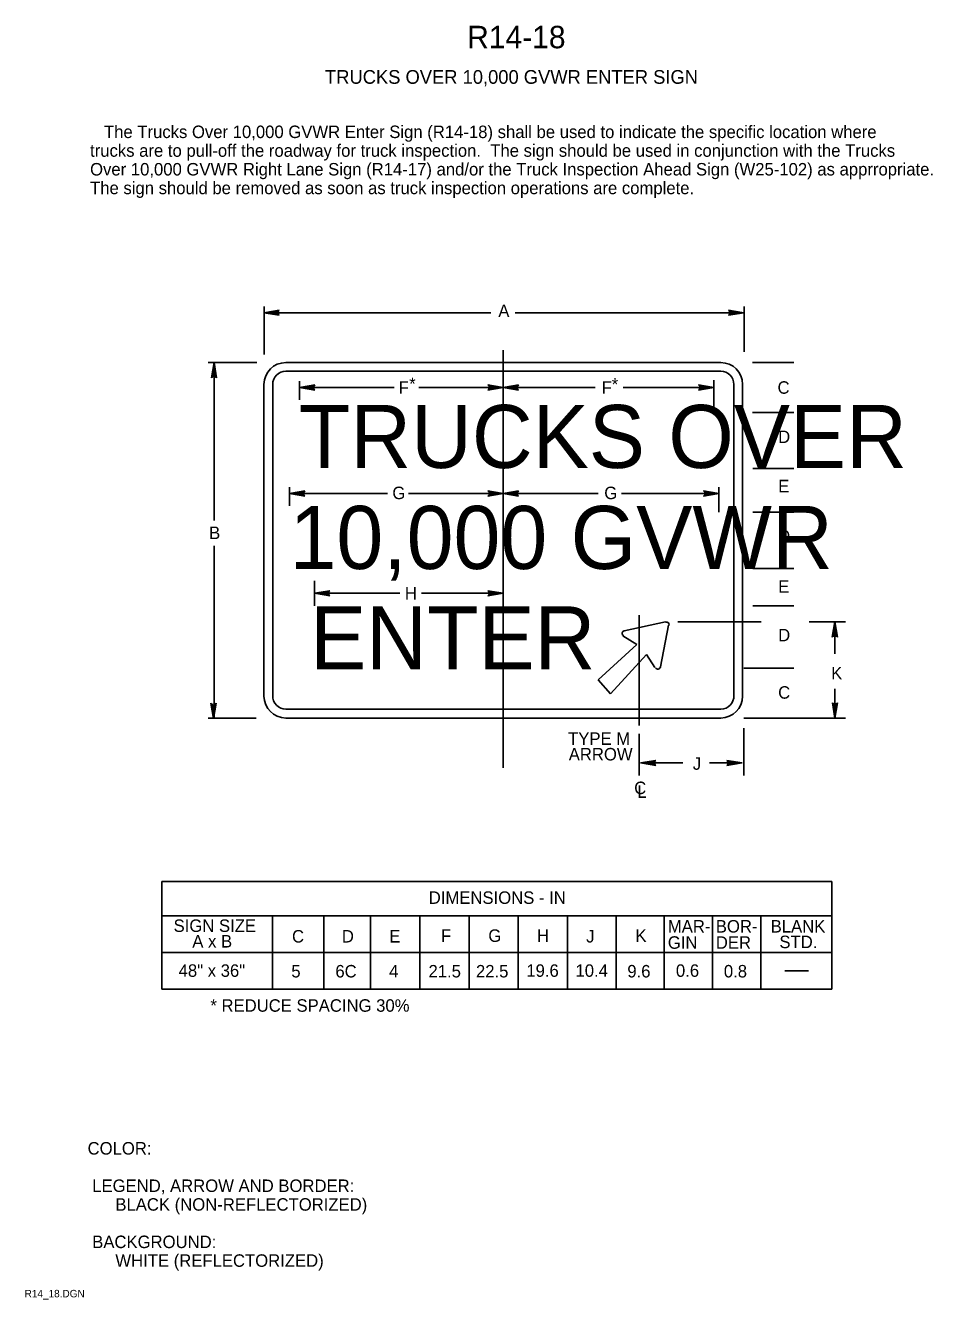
# Model space of a CAD drawing. Extents: x 0.013 to 0.195, y 0.004 to 0.259.
import ezdxf

# ---------------------------------------------------------------- set-up
doc = ezdxf.new("R2010")
doc.units = 0
for name, color, linetype in [('1', 7, 'Continuous'), ('11', 7, 'Continuous'), ('12', 7, 'Continuous'), ('3', 7, 'Continuous')]:
    doc.layers.add(name, color=color, linetype=linetype)

# ---------------------------------------------------------------- blocks, each defined once
blk = doc.blocks.new('RARROW')
at = {"layer": '3'}
for p, q in [((-2.156, 0.28500000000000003), (-2.2665, 0.384625)), ((-2.2665, 0.384625), (0, 0)), ((0, 0), (-2.2665, -0.379125)), ((-2.156, 0.28500000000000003), (-2.075625, 0.12075)), ((0, 0), (-2.156, 0.28500000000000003)), ((-2.14975, -0.2705), (0, 0)), ((-2.075625, 0.12075), (0, 0)), ((0, 0), (-2.074, -0.108)), ((-2.2665, -0.379125), (-2.14975, -0.2705)), ((-2.074, -0.108), (-2.14975, -0.2705))]:
    blk.add_line(p, q, dxfattribs=at)

msp = doc.modelspace()

# ---------------------------------------------------------------- linework, layer by layer
at = {"layer": '11'}
for p, q in [((0.064875, 0.19175), (0.152125, 0.19175)), ((0.0605, 0.187375), (0.0605, 0.124875)), ((0.1565, 0.187375), (0.1565, 0.124875)), ((0.064875, 0.1205), (0.152125, 0.1205))]:
    msp.add_line(p, q, dxfattribs=at)
for centre, radius, start, end in [((0.06487500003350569, 0.18737499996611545), 0.004375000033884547, 90, 180), ((0.1521250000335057, 0.18737500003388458), 0.0043749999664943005, 0, 90), ((0.0648749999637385, 0.12487499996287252), 0.004374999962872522, 180, 270), ((0.1521249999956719, 0.12487500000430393), 0.004375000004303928, 270, 0)]:
    msp.add_arc(centre, radius, start, end, dxfattribs=at)
at = {"layer": '12'}
for p, q in [((0.13275, 0.138), (0.14100000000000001, 0.13975)), ((0.141625, 0.139125), (0.14, 0.13075)), ((0.13525, 0.13525), (0.1325, 0.137)), ((0.1275, 0.128125), (0.13525, 0.13525)), ((0.13725, 0.13325), (0.13, 0.12537500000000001)), ((0.138875, 0.130625), (0.13725, 0.13325)), ((0.13, 0.12537500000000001), (0.1275, 0.128125))]:
    msp.add_line(p, q, dxfattribs=at)
for centre, radius, start, end in [((0.13284675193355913, 0.13747758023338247), 0.0005223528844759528, 101.7398388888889, 236.68377222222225), ((0.1412314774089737, 0.13922005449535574), 0.0005223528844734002, 348.2601611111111, 101.73982222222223), ((0.13948900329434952, 0.1308353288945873), 0.0005223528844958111, 213.3162277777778, 348.26016388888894)]:
    msp.add_arc(centre, radius, start, end, dxfattribs=at)
at = {"layer": '3'}
for p, q in [((0.106, 0.20175), (0.0605, 0.20175)), ((0.06054947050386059, 0.193375), (0.06054947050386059, 0.203)), ((0.110875, 0.20175), (0.15675, 0.20175)), ((0.1567994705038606, 0.193875), (0.1567994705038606, 0.203)), ((0.1085, 0.19425), (0.1085, 0.1105)), ((0.05904947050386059, 0.19175), (0.04929947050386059, 0.19175)), ((0.0505, 0.160125), (0.0505, 0.19175)), ((0.1585, 0.19175), (0.16675, 0.19175)), ((0.152125, 0.19), (0.064875, 0.19)), ((0.06225, 0.187375), (0.06225, 0.125)), ((0.067625, 0.188), (0.067625, 0.18425)), ((0.08660579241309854, 0.18675), (0.06767447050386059, 0.18675)), ((0.09154947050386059, 0.18675), (0.10854947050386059, 0.18675)), ((0.1269244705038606, 0.18675), (0.10854947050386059, 0.18675)), ((0.1325494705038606, 0.18675), (0.15075, 0.18675)), ((0.15075, 0.18825), (0.15075, 0.182)), ((0.15475, 0.125), (0.15475, 0.187375)), ((0.1585, 0.18175), (0.16675, 0.18175)), ((0.1585494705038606, 0.1705), (0.1667994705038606, 0.1705)), ((0.065625, 0.16675), (0.065625, 0.163)), ((0.15175, 0.16675), (0.15175, 0.16175)), ((0.08525, 0.1655), (0.065625, 0.1655)), ((0.0895, 0.1655), (0.1085, 0.1655)), ((0.1275494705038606, 0.1655), (0.10854947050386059, 0.1655)), ((0.13219027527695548, 0.1655), (0.15179947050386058, 0.1655)), ((0.1585494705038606, 0.16175), (0.1667994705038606, 0.16175)), ((0.0505, 0.155), (0.0505, 0.1205)), ((0.1585494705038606, 0.1505), (0.1667994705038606, 0.1505)), ((0.07062500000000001, 0.148), (0.07062500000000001, 0.14300000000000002)), ((0.08775000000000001, 0.1455), (0.07062500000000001, 0.1455)), ((0.092125, 0.1455), (0.1085, 0.1455)), ((0.13575, 0.11900000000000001), (0.13575, 0.14110487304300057)), ((0.1585494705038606, 0.14300000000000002), (0.1667994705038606, 0.14300000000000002)), ((0.14350000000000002, 0.13975), (0.16025, 0.13975)), ((0.177125, 0.13975), (0.169875, 0.13975)), ((0.17500000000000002, 0.133375), (0.17500000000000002, 0.13975)), ((0.15675, 0.1305), (0.16675, 0.1305)), ((0.1585494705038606, 0.1305), (0.1667994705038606, 0.1305)), ((0.17500000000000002, 0.1205), (0.17500000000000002, 0.12637500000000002)), ((0.05892447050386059, 0.1205), (0.04929947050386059, 0.1205)), ((0.064875, 0.12225), (0.152125, 0.12225)), ((0.15675, 0.1205), (0.177125, 0.1205)), ((0.1585494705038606, 0.1205), (0.1667994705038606, 0.1205)), ((0.15675, 0.11850000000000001), (0.15675, 0.109)), ((0.13575, 0.109), (0.13575, 0.1173495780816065)), ((0.136, 0.1115), (0.1445, 0.1115)), ((0.149875, 0.1115), (0.15637500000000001, 0.1115)), ((0.04, 0.08775000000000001), (0.174375, 0.08775000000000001)), ((0.04, 0.08775000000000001), (0.04, 0.066125)), ((0.174375, 0.08775000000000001), (0.174375, 0.066125)), ((0.174375, 0.080875), (0.04, 0.080875)), ((0.06223835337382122, 0.08081758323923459), (0.06223835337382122, 0.06606758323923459)), ((0.0725, 0.080875), (0.0725, 0.066125)), ((0.081875, 0.080875), (0.081875, 0.066125)), ((0.09175, 0.080875), (0.09175, 0.066125)), ((0.10162500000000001, 0.080875), (0.10162500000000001, 0.066125)), ((0.1115, 0.080875), (0.1115, 0.066125)), ((0.12136335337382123, 0.08081758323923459), (0.12136335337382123, 0.06744258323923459)), ((0.121375, 0.080875), (0.121375, 0.066125)), ((0.1311133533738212, 0.08081758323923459), (0.1311133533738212, 0.06606758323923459)), ((0.1407383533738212, 0.08081758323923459), (0.1407383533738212, 0.06744258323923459)), ((0.14075000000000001, 0.080875), (0.14075000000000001, 0.066125)), ((0.15048835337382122, 0.08081758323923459), (0.15048835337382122, 0.06606758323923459)), ((0.160125, 0.080875), (0.160125, 0.066125)), ((0.174375, 0.0735), (0.04, 0.0735)), ((0.16496499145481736, 0.06982506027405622), (0.16969091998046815, 0.06982506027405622)), ((0.174375, 0.066125), (0.04, 0.066125))]:
    msp.add_line(p, q, dxfattribs=at)
for centre, radius, start, end in [((0.06487500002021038, 0.18737499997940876), 0.002625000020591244, 90, 180), ((0.15212500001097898, 0.18737500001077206), 0.0026249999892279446, 0, 90), ((0.06493750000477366, 0.12493750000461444), 0.0026882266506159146, 178.66778055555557, 268.66778055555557), ((0.1520625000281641, 0.12493749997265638), 0.0026882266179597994, 271.3322194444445, 1.3322194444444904)]:
    msp.add_arc(centre, radius, start, end, dxfattribs=at)

# ---------------------------------------------------------------- block references
at = {"layer": '3', "xscale": 0.0013566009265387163, "yscale": 0.0013419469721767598}
for p, rotation in [((0.0605, 0.20175), 180), ((0.0505, 0.19175), 90), ((0.067625, 0.18675), 180), ((0.1085, 0.18675), 180), ((0.065625, 0.1655), 180), ((0.1085, 0.1655), 180), ((0.07062500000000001, 0.1455), 180), ((0.17500000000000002, 0.13975), 90), ((0.050375, 0.120375), -90), ((0.17500000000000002, 0.1205), -90), ((0.136, 0.1115), 180)]:
    msp.add_blockref('RARROW', p, dxfattribs=dict(at, rotation=rotation))
for p in [(0.15675, 0.20175), (0.1085, 0.18675), (0.15075, 0.18675), (0.1085, 0.1655), (0.15175, 0.1655), (0.1085, 0.1455), (0.15637500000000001, 0.1115)]:
    msp.add_blockref('RARROW', p, dxfattribs=at)

# ---------------------------------------------------------------- texts
at = {"layer": '1'}
for s, height, p in [('R14-18', 0.0045000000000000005, (0.10125, 0.25475000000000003)), ('TRUCKS OVER 10,000 GVWR ENTER SIGN', 0.00275025, (0.07275, 0.247625)), ('   The Trucks Over 10,000 GVWR Enter Sign (R14-18) shall be used to indicate the specific location where', 0.0024997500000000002, (0.025625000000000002, 0.23674975)), ('trucks are to pull-off the roadway for truck inspection.  The sign should be used in conjunction with the Trucks', 0.0024997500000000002, (0.025625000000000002, 0.233)), ('Over 10,000 GVWR Right Lane Sign (R14-17) and/or the Truck Inspection Ahead Sign (W25-102) as apprropriate.', 0.0024997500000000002, (0.025625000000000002, 0.22925025)), ('The sign should be removed as soon as truck inspection operations are complete.', 0.0024997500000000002, (0.025625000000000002, 0.2255005)), ('COLOR:', 0.0024997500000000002, (0.025125, 0.032999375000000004)), (' LEGEND, ARROW AND BORDER:', 0.0024997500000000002, (0.025125, 0.025499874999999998)), ('      BLACK (NON-REFLECTORIZED)', 0.0024997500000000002, (0.025125, 0.021750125)), (' BACKGROUND:', 0.0024997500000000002, (0.025125, 0.014250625)), ('      WHITE (REFLECTORIZED)', 0.0024997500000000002, (0.025125, 0.010500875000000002)), ('R14_18.DGN', 0.0015, (0.0125, 0.004375))]:
    msp.add_text(s, height=height, dxfattribs=at).set_placement(p)
at = {"layer": '12'}
for s, height, p in [('TRUCKS OVER', 0.01262475, (0.0675, 0.170625)), ('10,000 GVWR', 0.012637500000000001, (0.065625, 0.150375)), ('ENTER', 0.01262475, (0.06975, 0.13025))]:
    msp.add_text(s, height=height, dxfattribs=at).set_placement(p)
at = {"layer": '3'}
for s, p in [('A', (0.1075, 0.200875)), ('F', (0.08750000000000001, 0.1855)), ('*', (0.089625, 0.18625)), ('F', (0.12825, 0.1855)), ('*', (0.13025, 0.186125)), ('C', (0.1635, 0.1855)), ('D', (0.163625, 0.175625)), ('G', (0.08625000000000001, 0.164375)), ('G', (0.12875, 0.164375)), ('E', (0.163625, 0.16575)), ('B', (0.0495, 0.15637500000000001)), ('D', (0.163625, 0.15575)), ('E', (0.163625, 0.145625)), ('H', (0.08875, 0.14425)), ('D', (0.163625, 0.135875)), ('K', (0.17425000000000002, 0.12825)), ('C', (0.163625, 0.124375)), ('TYPE M', (0.1215, 0.115125)), ('ARROW', (0.121625, 0.112)), ('J', (0.1465, 0.110125)), ('C', (0.13475, 0.10525)), ('L', (0.135375, 0.1045)), ('DIMENSIONS - IN', (0.09355060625, 0.08325)), ('SIGN SIZE', (0.042375, 0.077625)), ('MAR-', (0.14150000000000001, 0.0775)), ('BOR-', (0.151125, 0.0775)), ('BLANK', (0.162125, 0.0775)), ('A x B', (0.046125, 0.0745)), ('C', (0.066125, 0.0755)), ('D', (0.076125, 0.0755)), ('E', (0.085625, 0.0755)), ('F', (0.096, 0.075625)), ('G', (0.1055, 0.075625)), ('H', (0.11525, 0.075625)), ('J', (0.12512500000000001, 0.0755)), ('K', (0.135, 0.075625)), ('GIN', (0.14150000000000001, 0.07425)), ('DER', (0.151125, 0.07425)), ('STD.', (0.163875, 0.074375)), ('48" x 36"', (0.043384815, 0.068625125)), ('5', (0.0659803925, 0.068500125)), ('6C', (0.074818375, 0.068500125)), ('4', (0.08559024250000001, 0.068500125)), ('21.5', (0.09349576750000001, 0.068500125)), ('22.5', (0.1030185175, 0.068500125)), ('19.6', (0.11311773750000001, 0.068625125)), ('10.4', (0.1229806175, 0.068625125)), ('9.6', (0.1333752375, 0.068500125)), ('0.6', (0.1431252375, 0.068625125)), ('0.8', (0.1527366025, 0.068500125)), ('* REDUCE SPACING 30%', (0.04975, 0.061625))]:
    msp.add_text(s, height=0.0024997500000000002, dxfattribs=at).set_placement(p)

doc.saveas('drawing.dxf')
